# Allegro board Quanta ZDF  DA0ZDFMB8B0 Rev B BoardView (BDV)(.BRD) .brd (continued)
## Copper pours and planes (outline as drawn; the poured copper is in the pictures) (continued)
N60703527 on TOP (solid shape): 41.94,43.52 41.94,41.76 41.88,41.7 41.37,41.7 41.29,41.68 41.23,41.61 40.19,41.61 40.11,41.69 40.11,43.59 40.19,43.67 41.79,43.67
N60721669 on TOP (solid shape): 4.18,39.49 5.12,39.49 5.89,38.72 5.89,38.61 6.21,38.3 6.21,34.93 6.84,34.3 6.84,27.95 6.71,27.82 6.08,27.82 5.82,28.07 5.82,33.28 4.94,34.17 4.94,37.22 3.54,38.61 3.54,39.25 3.79,39.5 4.17,39.5
N60727876 on TOP (solid shape): 10.82,55.42 10.82,55.18 10.94,55.06 10.94,54.99 10.77,54.82 7.29,54.82 7,54.53 6.47,54.53 6.38,54.62 6.38,55 6.57,55.18 7.17,55.18 7.27,55.08 8.58,55.08 9.22,55.72 10.52,55.72
N60727876 on TOP (solid shape): 7.23,57.58 8.67,57.58 8.94,57.85 9.27,57.85 9.32,57.83 9.38,57.83 9.43,57.83 9.48,57.85 9.77,57.85 9.99,57.62 9.99,57.35 9.91,57.26 9.52,57.26 9.47,57.32 7.26,57.32 7.17,57.23 6.66,57.23 6.51,57.38 6.51,57.71 6.66,57.87 6.94,57.87
N60727876 on TOP (solid shape): 19.95,49.07 20.57,48.92 21.2,48.87 21.96,48.87 22.04,48.79 22.04,47.97 21.62,47.55 21.54,47.55 21.43,47.51 21.39,47.4 21.39,46.54 20,46.54 19.85,46.69 19.85,49 19.92,49.08
N60727876 on BOTTOM (solid shape): outline of 105 points within 6.47,46.69 22.21,60.35
N60727876 on IN2 (solid shape): 9.17,57.92 9.38,57.83 9.59,57.92 9.71,57.92 10,57.64 10,57.3 10.44,56.86 10.44,56.58 10.52,56.49 12.26,54.76 12.26,53.44 13.2,52.5 14.08,52.5 15.52,51.06 17.61,51.06 19.1,49.46 21.2,48.87 21.58,48.87 21.61,48.84 21.79,48.84 22,48.62 22,47.71 21.8,47.5 21.8,47.46 21.74,47.39 21.65,47.4 21.43,47.33 21.3,47.14 21.29,47.1 19.01,47.1 18.45,47.66 17.25,47.66 13.91,51.01 13.91,51.13 13.89,51.2 13.85,51.26 12.18,52.94 11.52,53.6 11.52,54.49 11.51,54.56 11.47,54.62 11.35,54.73 11.22,54.92 11.01,55 10.94,54.99 10.87,54.97 10.04,54.97 9.63,55.38 9.63,55.76 9.94,56.06 9.94,56.8 9.41,57.34 8.69,57.34 8.64,57.38 8.64,57.74 8.83,57.92
N60727876 on IN3 (solid shape): outline of 158 points within 6.43,53.94 11.54,60.24
N60727876 on IN5 (solid shape): outline of 144 points within 8.62,47.12 22.21,61.35
N60839367 on BOTTOM (solid shape): 62.04,42.4 62.04,39.66 61.16,38.78 59.27,38.78 59.27,40.09 58.96,40.39 58.5,40.39 58.25,40.65 58.25,42.53 58.38,42.65 61.78,42.65
N60918429 on BOTTOM (solid shape): 94.34,11.74 94.34,8.64 93.96,8.26 89.44,8.26 88.8,8.9 88.8,11.82 88.93,11.94 94.14,11.94
N61018148 on TOP (solid shape): 72.22,40.48 72.9,40.48 72.98,40.39 72.98,40.06 72.83,39.91 71.94,39.91 71.71,39.68 71.71,38.51 71.66,38.46 71.31,38.46 71.18,38.59 71.18,40.44 71.31,40.57 72.13,40.57
N61018186 on TOP (solid shape): 69.32,37.85 69.32,35.69 69.71,35.31 72.25,35.31 72.25,35.06 72.2,35.01 71.94,35.01 71.76,34.83 70.93,34.83 70.9,34.8 70.81,34.8 70.81,34.19 70.68,34.07 69.55,34.07 69.2,34.42 68.56,34.42 68.18,34.8 67.67,34.8 67.67,35.16 67.72,35.21 67.72,37.87 67.83,37.98 69.2,37.98
N61018194 on TOP (solid shape): 71.15,37.83 71.15,37.5 71.41,37.24 71.59,37.24 71.64,37.19 71.64,36.28 71.61,36.25 70.93,36.25 70.75,36.07 70.75,35.62 70.65,35.52 69.76,35.52 69.66,35.62 69.66,37.95 69.76,38.06 70.93,38.06
N61018215 on TOP (solid shape): 72.98,37.19 72.98,35.91 72.96,35.84 72.96,35.77 72.96,35.49 72.92,35.49 72.84,35.53 72.75,35.54 72.67,35.53 72.59,35.49 71.08,35.49 71,35.57 71,35.97 71.08,36.05 72.4,36.05 72.53,36.18 72.53,37.22 72.6,37.29 72.88,37.29
N61036583 on TOP (solid shape): 128.79,29.95 129.29,29.95 129.41,29.83 129.41,29.79 129.41,29.41 129.41,29.36 129.37,29.32 128.65,29.32 128.62,29.34 127.41,30.55 127.41,30.61 127.16,30.87 126.35,30.87 126.3,30.92 126.3,31.09 127.09,31.09 127.09,31.1 127.64,31.1
N61047769 on TOP (solid shape): 95.49,10.93 97.65,10.93 97.77,10.8 97.77,9.91 97.11,9.25 95.84,9.25 95.36,9.73 95.36,9.79 94.98,10.17 93.4,10.17 93.39,10.17 93.34,10.19 93.29,10.2 92.58,10.2 92.52,10.2 92.47,10.17 92.46,10.17 92.06,10.17 91.42,9.53 91.42,8.52 91.3,8.39 90.53,8.39 90.41,8.52 90.41,9.91 91.55,11.06 95.36,11.06
N61120403 on BOTTOM (solid shape): 94.52,19.13 94.52,18.93 95.1,18.34 95.1,16.52 94.89,16.3 93.56,16.3 93.19,16.67 92.42,16.67 92.4,16.69 92.4,18.07 92.3,18.16 91.87,18.16 91.83,18.2 88.15,18.2 88.15,18.2 88.1,18.31 87.99,18.35 86.51,18.35 86.41,18.46 86.41,19.17 86.67,19.44 94.22,19.44
N61120560 on BOTTOM (solid shape): 102.54,18.6 102.54,18.39 102.32,18.17 102.19,18.17 101.99,18.37 100.87,18.37 100.82,18.42 100.82,18.78 100.87,18.83 102.31,18.83
N61120590 on BOTTOM (solid shape): 92.23,17.92 92.23,16.61 91.28,16.61 91.25,16.64 91.25,17.9 91.31,17.96 92.18,17.96
N61120594 on BOTTOM (solid shape): 102.1,21.06 102.1,19.06 102.05,19.01 100.92,19.01 100.87,19.06 100.87,20.01 101.44,20.57 101.44,21.18 101.58,21.31 101.85,21.31
N61126400 on BOTTOM (solid shape): 98.34,21.42 98.34,20.43 98.08,20.18 98.08,18.87 98.13,18.83 99.2,18.83 99.27,18.75 99.27,18.37 98,18.37 97.75,18.62 97.75,18.64 97.62,18.77 97.05,18.77 96.82,19 96.82,19.23 96.25,19.79 96.25,21.42 96.38,21.55 98.21,21.55
N61126408 on BOTTOM (solid shape): 97.54,18.52 97.54,18.27 97.65,18.17 99.22,18.17 99.25,18.14 99.25,17.71 98.23,17.71 98.08,17.56 98.08,16.86 98.08,15.75 97.98,15.65 95.74,15.65 95.46,15.93 95.46,18.45 95.61,18.6 97.47,18.6
N61129418 on TOP (solid shape): 15.6,14.43 15.6,13.09 16.05,12.64 16.05,12.08 16,12.02 14.66,12.02 14.59,12.1 14.59,13.85 15.06,14.32 15.27,14.53 15.5,14.53
N61235166 on TOP (solid shape): 128.95,17.31 128.95,16.52 128.99,16.52 129.01,16.44 129.01,16.01 129.27,15.75 129.27,15.37 129.25,15.36 128.75,15.36 128.55,15.16 127.82,15.16 127.74,15.24 127.74,17.23 127.85,17.34 128.93,17.34
N61235168 on TOP (solid shape): 128.25,20.2 128.89,20.2 129.01,20.07 129.01,19.44 128.89,19.31 128.89,18.55 127.17,18.55 127.13,18.59 127.13,19.04 127.13,19.16 127.12,19.18 127.05,19.28 126.96,19.34 126.95,19.34 126.86,19.43 126.86,20.33 127.07,20.54 127.92,20.54
N61235186 on TOP (solid shape): 132.97,17.38 133.02,17.38 133.09,17.38 133.15,17.36 133.21,17.35 133.39,17.35 133.71,17.02 133.71,15.72 133.67,15.67 131.85,15.67 131.83,15.7 131.74,15.85 131.58,15.9 131.53,15.9 131.43,16.01 130.67,16.01 130.28,16.39 130.28,16.44 130.31,16.52 130.35,16.52 130.35,17.37 130.84,17.37 130.89,17.37 130.93,17.4 130.95,17.41 132.92,17.41
N61235189 on TOP (solid shape): 132.82,20.33 132.82,18.68 132.57,18.42 130.95,18.42 130.93,18.43 130.89,18.45 130.84,18.46 130.35,18.46 130.35,19.31 130.31,19.31 130.28,19.38 130.28,19.44 131.14,20.3 131.19,20.3 131.25,20.28 131.3,20.27 131.35,20.28 131.41,20.3 131.49,20.3 131.53,20.3 131.58,20.33 131.68,20.33 131.89,20.54 132.61,20.54
N61287435 on TOP (solid shape): 121.27,30.86 121.27,29.14 121.24,29.11 120.81,29.11 120.2,29.72 120.2,30.86 120.33,30.99 121.14,30.99
N61354726 on BOTTOM (solid shape): 28.84,38.66 28.89,38.6 28.98,38.57 29.31,38.57 29.4,38.48 29.4,38.06 29.35,38 27.36,38 27.31,38.06 27.31,38.61 27.36,38.66
N61354730 on BOTTOM (solid shape): 27.83,40.6 27.9,40.59 27.97,40.6 28.04,40.62 28.46,40.62 28.53,40.54 28.53,39.96 27.87,39.3 27.87,38.92 27.8,38.84 26.7,38.84 26.65,38.89 26.65,39.86 27.41,40.62 27.76,40.62
N61611783 on TOP (solid shape): 69.68,51.34 70.49,51.34 70.59,51.24 70.59,50.7 70.52,50.63 69.21,50.63 69.07,50.77 68.42,50.77 68.31,50.89 68.31,51.87 68.41,51.97 69.05,51.97
N61611820 on TOP (solid shape): 70.19,53.65 70.19,53.12 70.59,52.71 70.59,51.64 70.49,51.54 69.78,51.54 69.01,52.31 69.01,53.69 69.02,53.7 70.14,53.7
N61723163 on BOTTOM (solid shape): 98.03,13.16 98.03,12.55 97.9,12.43 97.42,12.43 97.29,12.55 97.29,12.76 97.15,12.9 95.37,12.9 95.36,12.91 95.36,13.47 97.72,13.47
N61762663 on BOTTOM (solid shape): 60.51,18.93 61.27,18.93 62.42,17.79 62.8,17.79 63.03,17.56 63.03,16.59 63.41,16.21 65.92,16.21 65.95,16.19 65.95,15.96 63.48,15.96 63.23,15.7 61.65,15.7 61.32,16.03 58.07,16.03 57.87,16.24 57.87,18.65 57.97,18.75 57.97,19.31 58.16,19.5 59.94,19.5
N61762731 on BOTTOM (solid shape): 68.49,19.82 68.49,18.37 67.68,17.57 67.68,16.44 67.61,16.38 66.71,16.38 66.66,16.42 66.66,16.67 66.75,16.76 66.89,16.76 67.05,16.93 67.05,17.88 67.65,18.49 67.65,19.76 67.77,19.88 68.43,19.88
N61762766 on BOTTOM (solid shape): 71.78,19.72 71.78,18.54 71.13,17.89 71.13,11.89 70.65,11.41 68.87,11.41 68.69,11.59 68.69,13.75 67.65,14.79 66.15,14.79 66.15,16.06 66.28,16.19 67.62,16.19 67.66,16.22 67.68,16.22 67.83,16.38 67.83,17.5 67.93,17.61 69.76,17.61 71.12,18.97 71.12,19.65 71.26,19.79 71.7,19.79
N61762770 on BOTTOM (solid shape): 70.98,10.98 70.98,10.19 70.8,10.01 68.61,10.01 68.54,10.09 68.54,11 68.66,11.13 70.82,11.13
N61762831 on BOTTOM (solid shape): 75.95,19.39 75.95,15.7 76.06,15.6 76.06,14.56 76.23,14.38 76.23,11.56 76.11,11.44 71.46,11.44 71.31,11.59 71.31,17.79 71.97,18.45 71.97,19.59 72.04,19.67 75.67,19.67
N61763881 on BOTTOM (solid shape): 45.96,32.06 45.96,31.55 46.67,30.84 47.91,30.84 48.45,30.3 48.45,29.93 48.83,29.55 48.83,29.52 48.98,29.37 51.27,29.37 51.29,29.34 51.29,29.17 51.24,29.11 47.86,29.11 47.81,29.17 46.67,29.17 46.49,28.99 43.04,28.99 42.99,29.04 42.99,30.54 43.02,30.54 43.13,30.58 43.17,30.69 43.17,31.92 43.25,32 45.07,32 45.31,32.24 45.78,32.24
N61763949 on BOTTOM (solid shape): 52.34,34.41 52.34,33.85 53.29,32.9 53.29,29.86 52.98,29.55 52.04,29.55 51.99,29.6 51.99,29.93 52.02,29.96 52.22,29.96 52.7,30.43 52.7,32.75 52.11,33.34 51.78,33.34 51.4,33.72 51.4,34.43 51.48,34.51 52.24,34.51
N61763986 on BOTTOM (solid shape): 55.46,34.07 55.46,33.28 56.12,32.62 56.12,27.9 55.86,27.64 55.86,26.5 55.69,26.32 54.64,26.32 54.29,26.68 51.77,26.68 51.47,26.98 51.47,29.09 51.52,29.14 52.94,29.14 53.12,29.32 53.12,29.32 53.39,29.59 53.39,29.61 53.44,29.66 53.44,29.79 53.44,29.79 53.44,32.54 53.57,32.67 54.24,32.67 54.87,33.31 54.87,34.02 54.97,34.12 55.41,34.12
N61763990 on BOTTOM (solid shape): 58.25,27.23 58.25,26.35 58.2,26.3 56.14,26.3 56.09,26.35 56.09,27.26 56.17,27.34 58.15,27.34
N61764017 on BOTTOM (solid shape): 60.66,33.15 60.89,33.15 60.97,33.08 60.97,32.44 61.45,31.96 61.45,26.68 61.32,26.55 60.26,26.55 60,26.8 60,27.54 59.67,27.87 57.21,27.87 56.75,28.33 56.75,34.19 56.87,34.31 57.54,34.31 57.65,34.36 57.69,34.46 57.69,34.54 57.78,34.54 57.79,34.55 59.27,34.55
N61796219 on TOP (solid shape): 71.32,9.53 71.32,9.34 72.08,8.58 72.08,8.16 71.97,8.05 70.09,8.05 70.02,8.12 70.02,8.89 70.11,8.98 70.58,8.98 70.76,9.17 70.76,9.31 70.77,9.36 70.77,9.46 70.76,9.5 70.87,9.6 71.25,9.6

Small or netless copper shapes (teardrops, artwork), in the pictures only: 57 on TOP, 10 on BOTTOM, 22 on IN1, 58 on IN2, 1 on IN3, 24 on IN4, 2 on IN5

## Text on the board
Ref Des/Silkscreen Bottom: DA0ZDFMB8B0  REV:B | Please do not print out the lines with 0.39mils/0.01mm in width
User.Comments: 69,5 | 30x32 | 118x157
Ref Des/Silkscreen Top: Please do not print out the lines with 0.39mils/0.01mm in width | DA0ZDFMB8B0 REV:B | MODEL:ZDF
User.32: 153,3 | 69,5
User.33: REV:A-1
User.45: Excess check:Apr 28 09:40:14 2020 | No Route Under Component:Apr 28 09:55:14 2020 | PadStack_Check:Apr 28 09:31:44 2020 | XY-Check acute:Apr 28 09:43:01 2020 | XY-Dxf to pin check:Apr 28 09:34:42 2020 | XY-Etch cross-IN2-GND:Apr 28 09:50:37 2020 | XY-Etch cross-IN3-IN4:Apr 28 09:50:42 2020 | XY-Etch cross-IN5-BOTTOM:Apr 28 09:50:45 2020 | XY-Etch cross-TOP-IN1:Apr 28 09:50:34 2020 | XY-Excess check:Apr 28 09:40:14 2020 | XY-NO Route Under Component:Apr 28 09:55:14 2020 | XY-Outline check:Apr 28 09:55:22 2020 | XY-PadStack_Check:Apr 28 09:31:44 2020 | XY-Prop check:Apr 28 09:50:28 2020 | XY-bbvia check:Apr 28 09:51:56 2020 | XY-shape min check:Apr 28 09:28:39 2020 | XY-via check:Apr 28 09:51:02 2020 | bbvia check:Apr 28 09:51:56 2020 | check acute:Apr 28 09:43:01 2020 | dxf to pin check:Apr 28 09:34:42 2020 | etch cross-IN2-GND:Apr 28 09:50:37 2020 | etch cross-IN3-IN4:Apr 28 09:50:42 2020 | etch cross-IN5-BOTTOM:Apr 28 09:50:45 2020 | etch cross-TOP-IN1:Apr 28 09:50:34 2020 | outline check:Apr 28 09:55:22 2020 | prop check:Apr 28 09:50:28 2020 | shape min check:Apr 28 09:28:39 2020 | via check:Apr 28 09:51:02 2020 | FIGURE | TYPE | Circle | SIZE | 4.0 | 8.0 | DRILL CHART: TOP to IN1 | ALL UNITS ARE IN MILS | DRILL CHART: IN1 to IN2 | DRILL CHART: IN2 to IN4 | DRILL CHART: IN4 to IN5 | DRILL CHART: IN5 to BOTTOM | PLATED | ROTATION | - | QTY | 3216 | 2232 | 498 | 2730 | 1850 | 1498 | 147 | 1262 | 1409 | Oblong | 55.0x24.0 | 57.0x24.0 | 63.0x24.0 | 10.0 | 14.0 | 18.0 | 28.0 | 110.0 | 118.0 | 177.0 | 32.0 | DRILL CHART: TOP to BOTTOM | NON-PLATED | 0.000 | 90.000 | 7 | 2 | 1 | 13 | 576 | 12 | 4 | 600 | TOTAL HOLES:
